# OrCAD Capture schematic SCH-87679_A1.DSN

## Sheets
1 4. BRKT-Sensors: size B; title: FRDM-STBI-A8971; rev: A1; company: NXP Semiconductors; note: SCH-87679 PDF: SPF-87679; note: 6501 William Cannon Drive West; note: Austin, TX 78735-8598
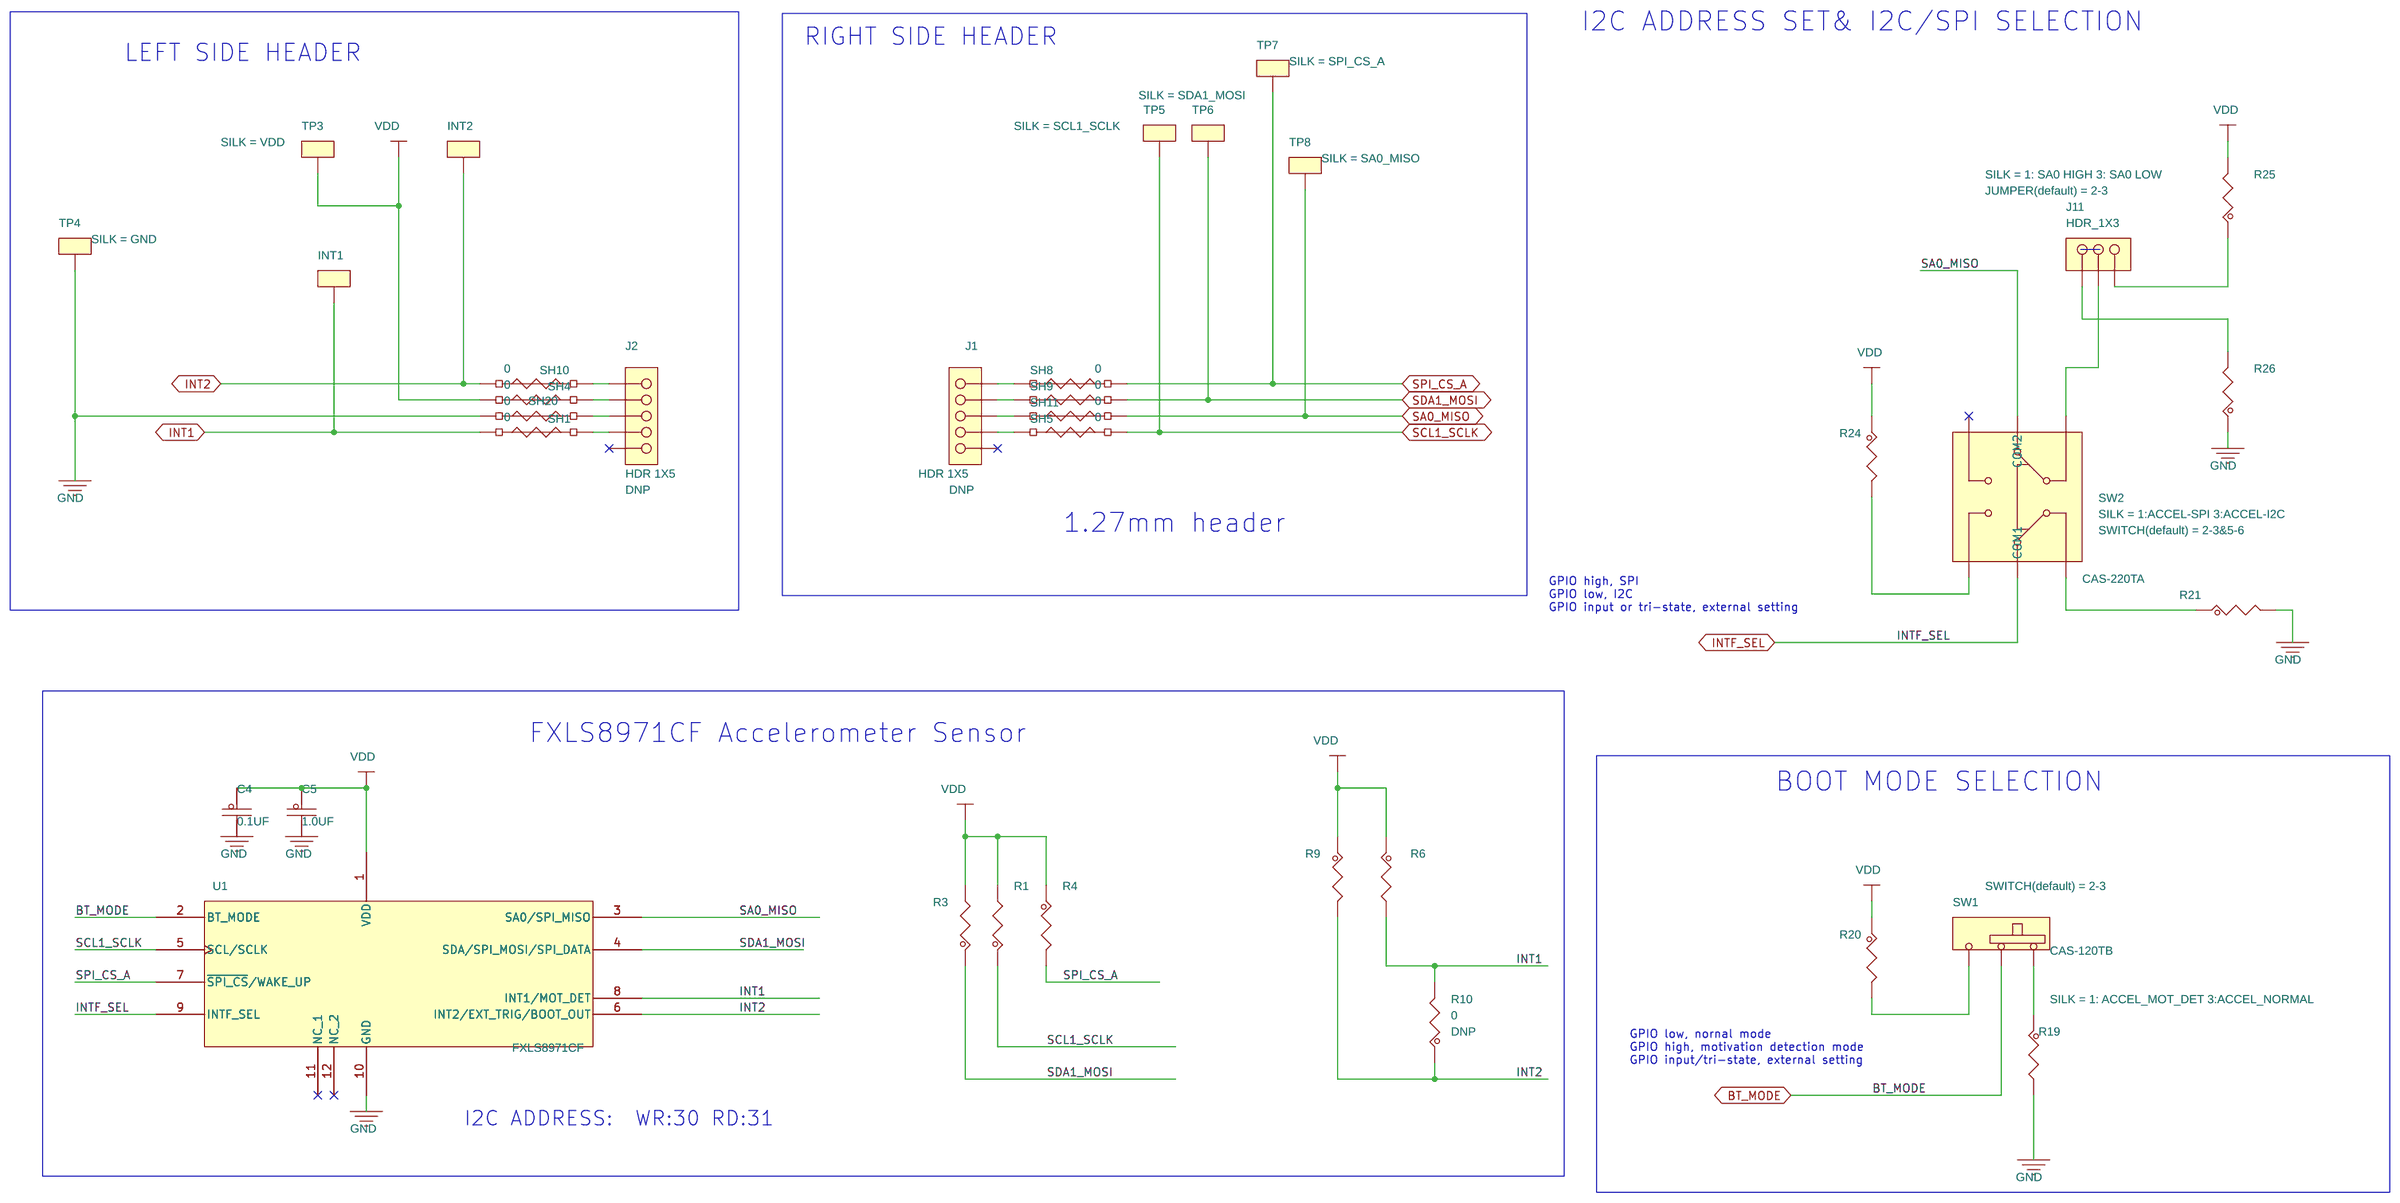
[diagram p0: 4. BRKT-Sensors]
2 1. Title Page
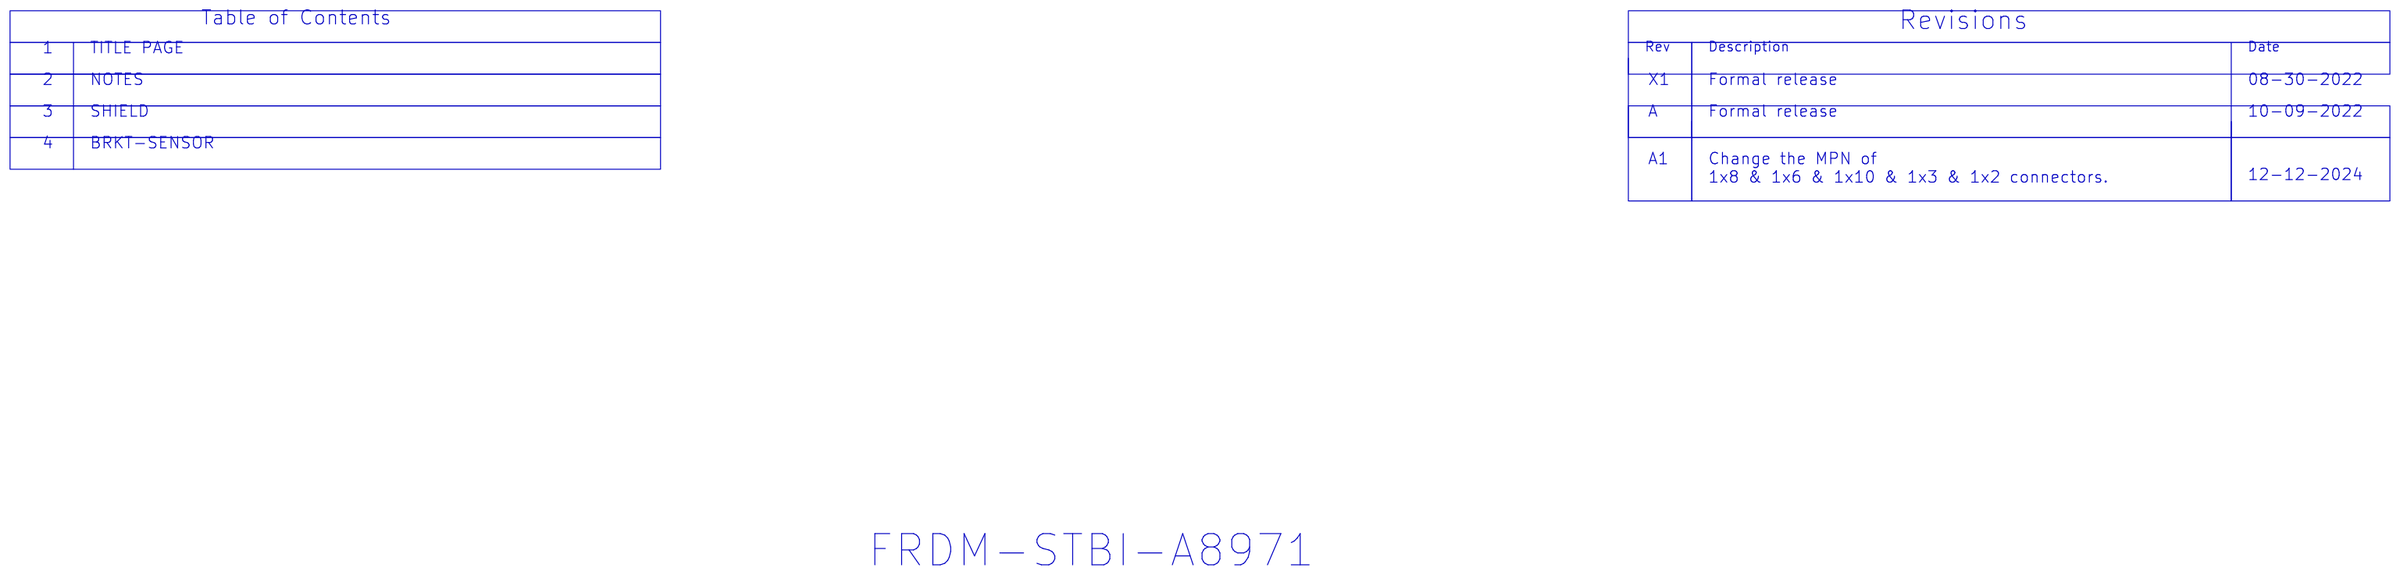
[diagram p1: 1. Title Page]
3 2. Notes
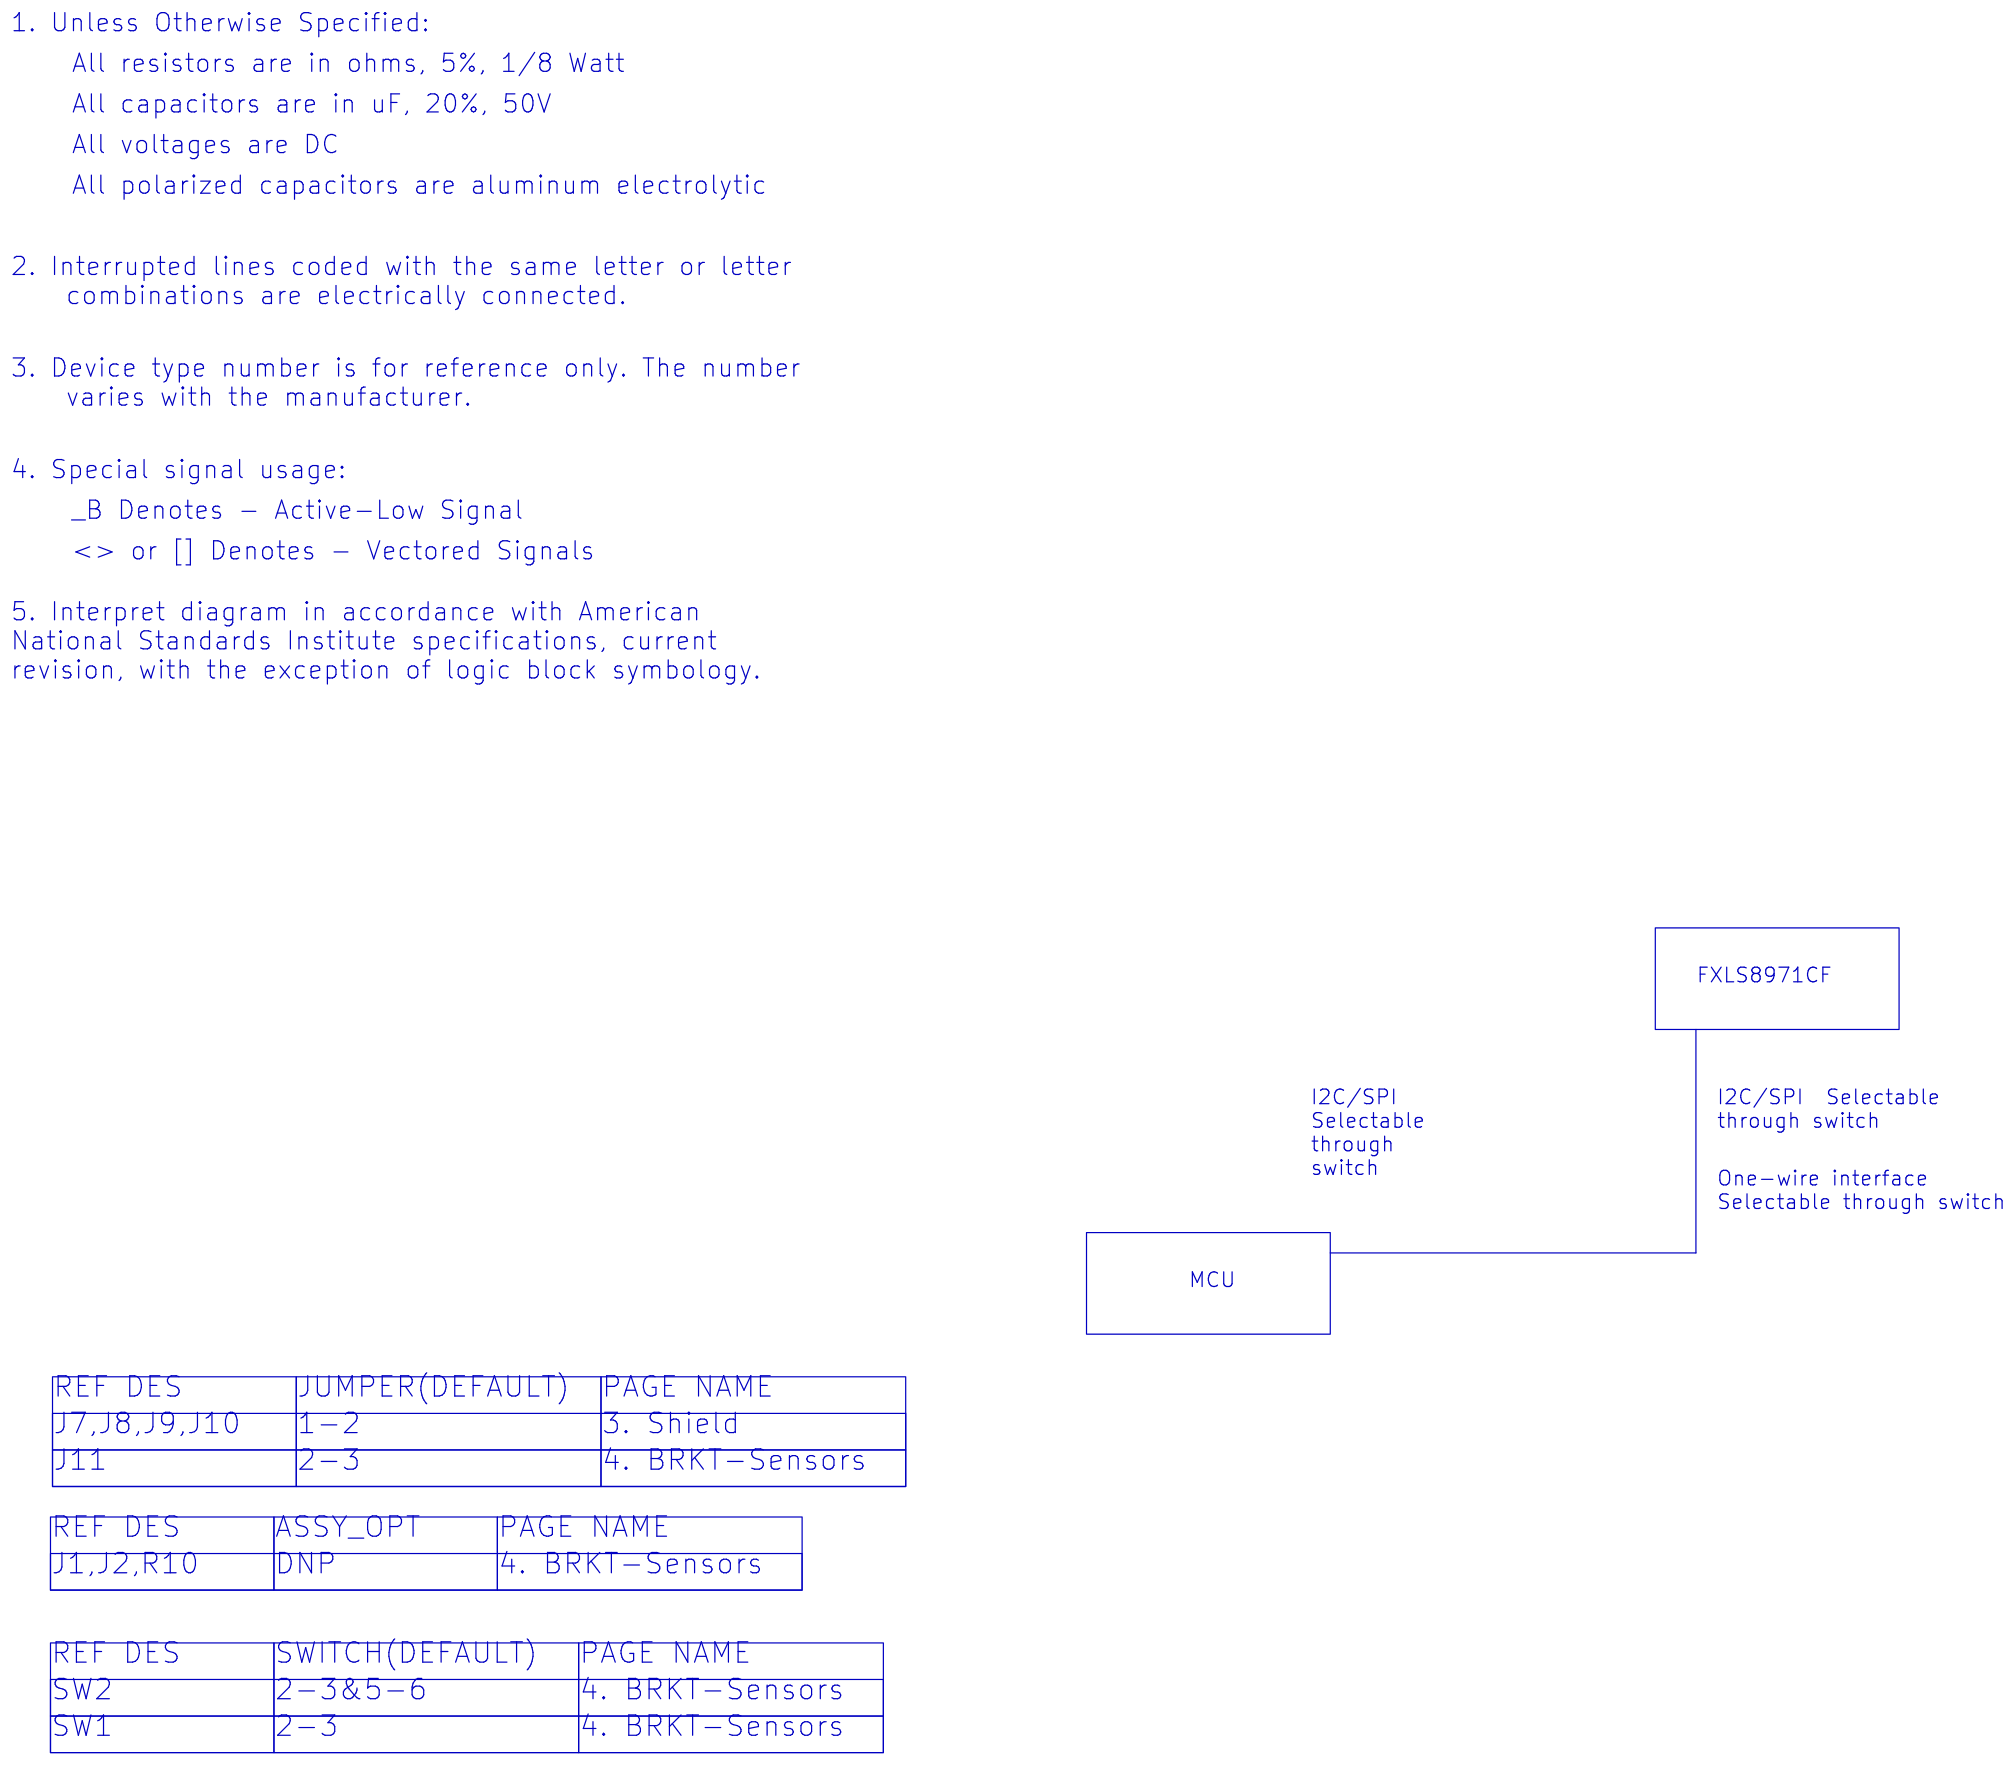
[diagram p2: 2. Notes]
4 3. Shield: size B
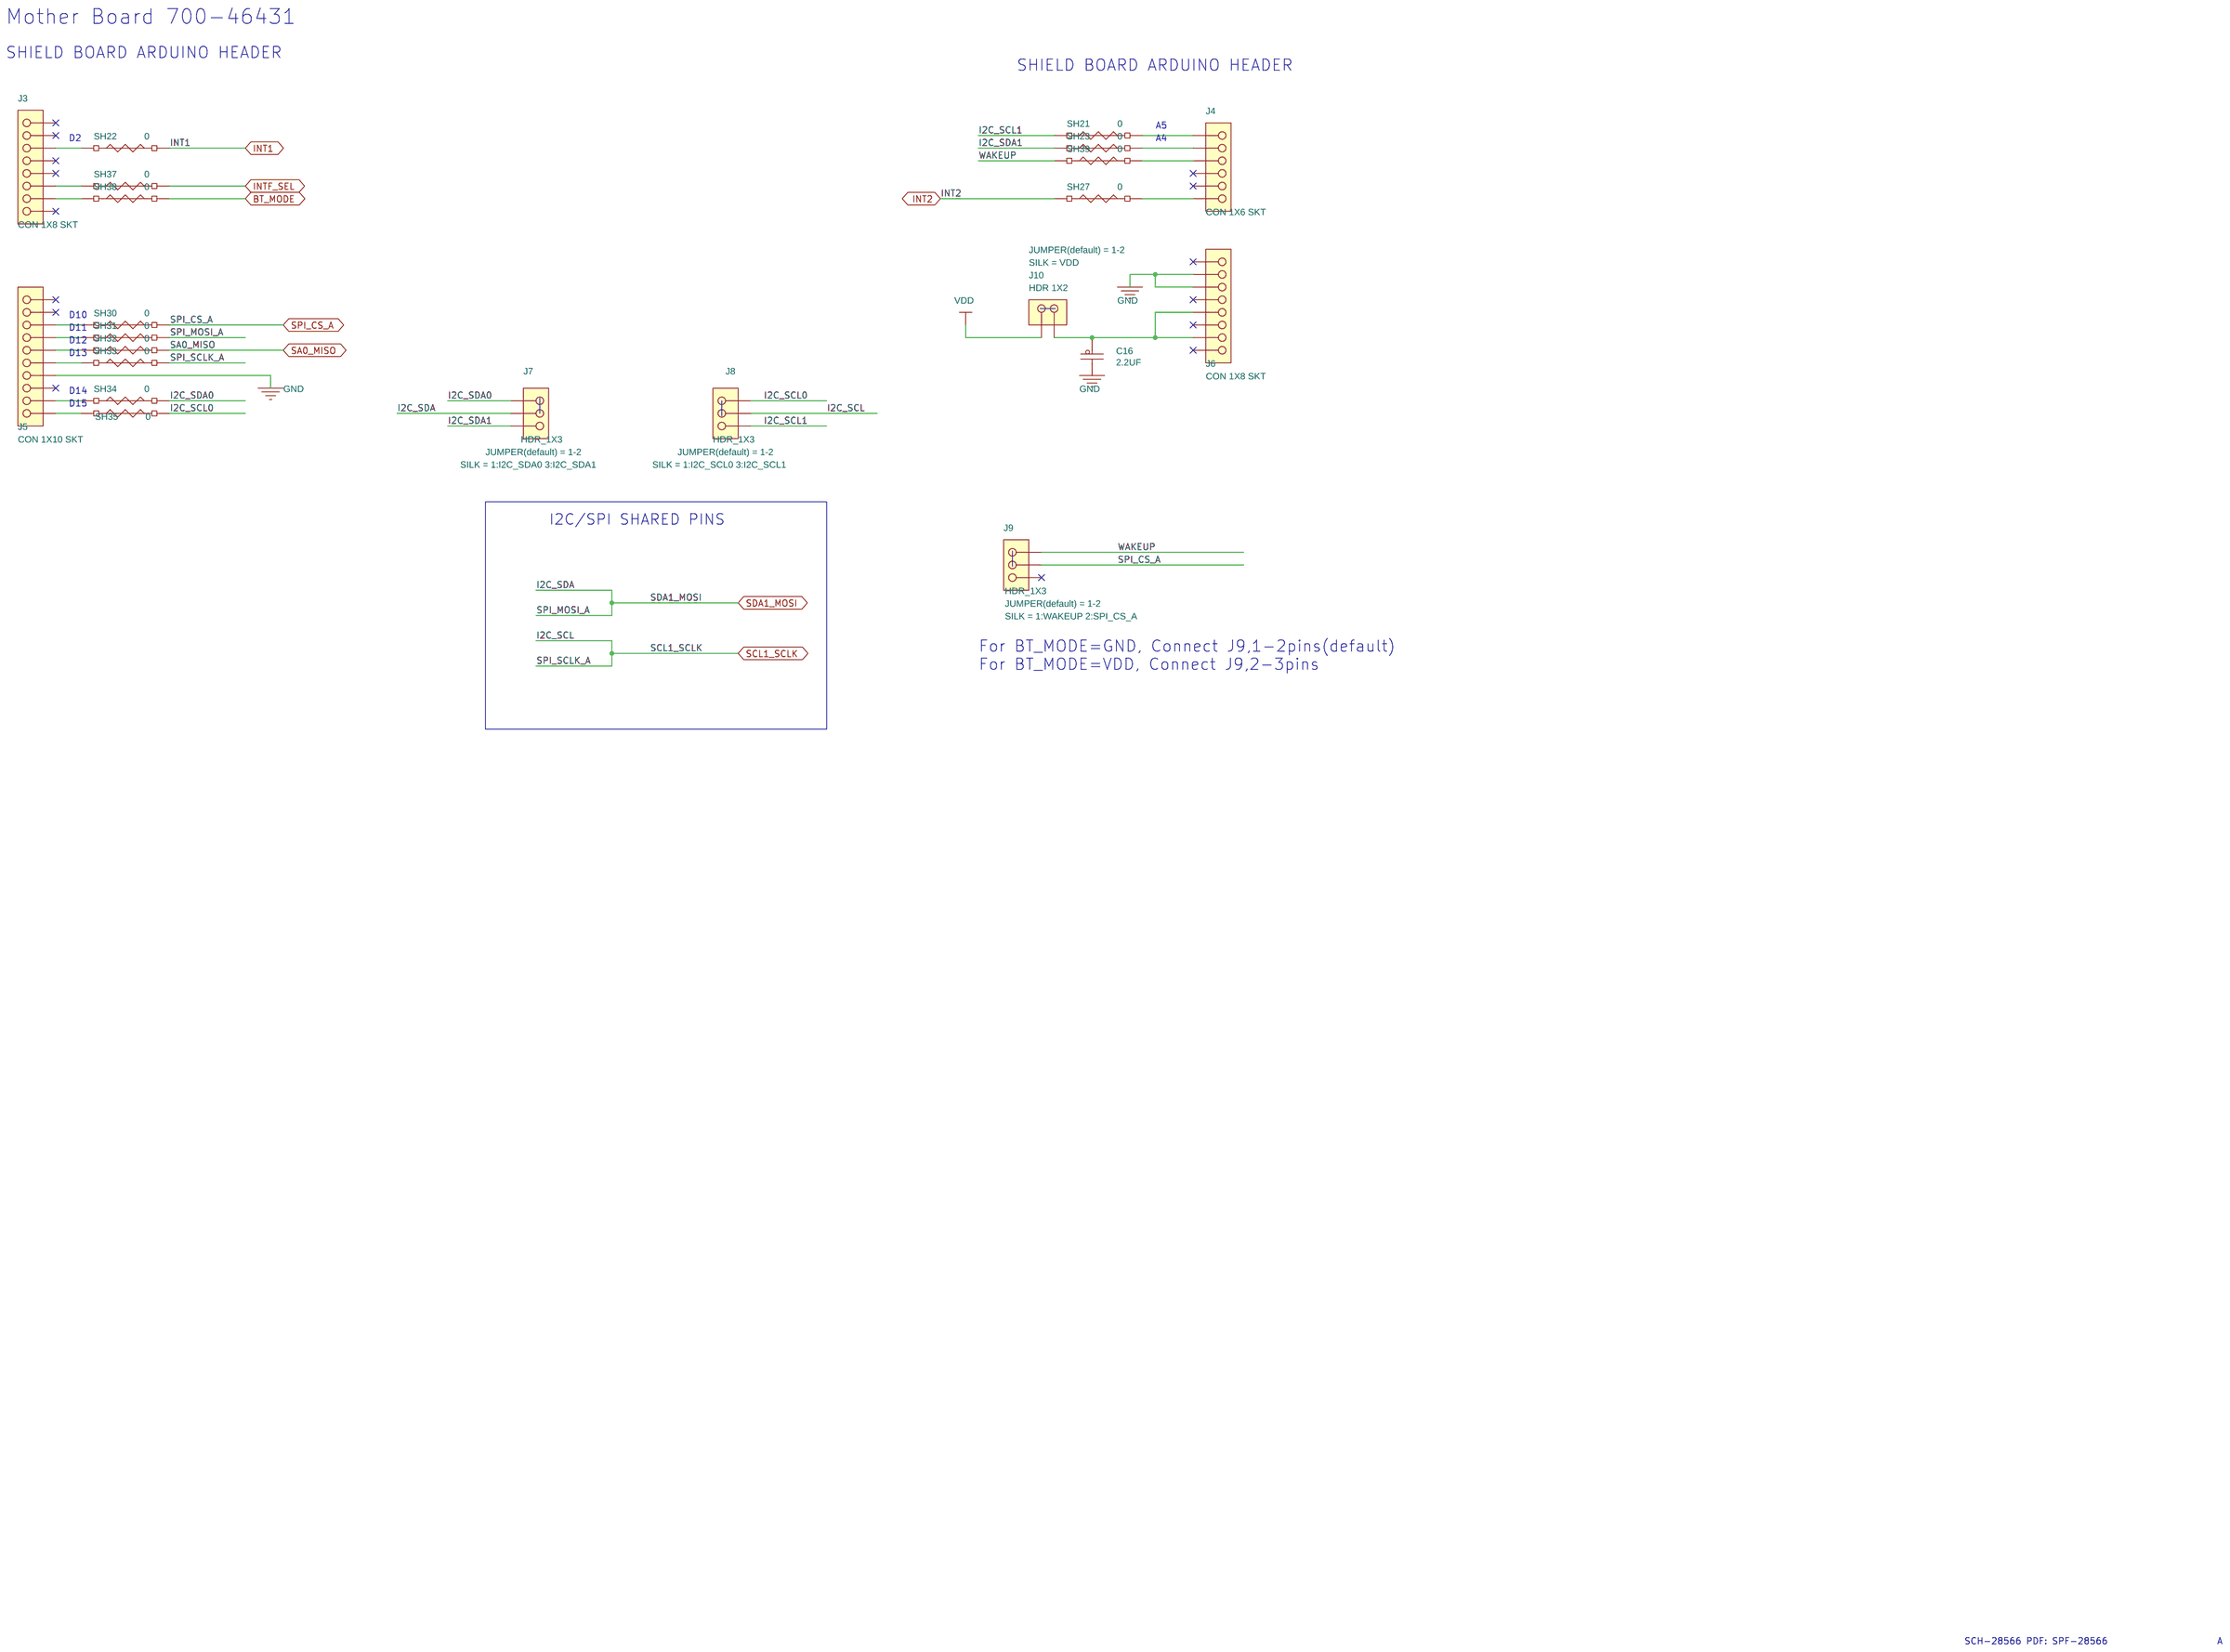
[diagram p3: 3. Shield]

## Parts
sheet 3. Shield
C16  2.2UF  [CC0402_25]
J3  CON 1X8 SKT  [con_skt1x8_th_394l]
J4  CON 1X6 SKT  [con_skt1x6_th_394l]
J5  CON 1X10 SKT  [hdr_1x10_2p54_341h]
J6  CON 1X8 SKT  [con_skt1x8_th_394l]
J7  HDR_1X3  [hdr103_330h]
J8  HDR_1X3  [hdr103_330h]
J9  HDR_1X3  [hdr103_330h]
J10  HDR 1X2  [hdr1x2_50mil]
SH21  0  [SH0201]
SH22  0  [SH0201]
SH23  0  [SH0201]
SH27  0  [SH0201]
SH30  0  [SH0201]
SH31  0  [SH0201]
SH32  0  [SH0201]
SH33  0  [SH0201]
SH34  0  [SH0201]
SH35  0  [SH0201]
SH37  0  [SH0201]
SH38  0  [SH0201]
SH39  0  [SH0201]
sheet 4. BRKT-Sensors
C4  0.1UF  [CC0402_25]
C5  1.0UF  [CC0402_25]
INT1  0805  [testpoint_122x049mil]
INT2  0805  [testpoint_122x049mil]
J1  HDR 1X5  [hdr1x5_50_th]
J2  HDR 1X5  [hdr1x5_50_th]
J11  HDR_1X3  [hdr103_330h]
R1  4.7K  [RC0603]
R3  4.7K  [RC0603]
R4  10K  [RC0603]
R6  10K  [RC0603]
R9  10K  [RC0603]
R10  0  [RC0603]
R19  10K  [RC0603]
R20  10K  [RC0603]
R21  10K  [RC0603]
R24  10K  [RC0603]
R25  10K  [RC0603]
R26  10K  [RC0603]
SH1  0  [SH0201]
SH4  0  [SH0201]
SH5  0  [SH0201]
SH8  0  [SH0201]
SH9  0  [SH0201]
SH10  0  [SH0201]
SH11  0  [SH0201]
SH20  0  [SH0201]
SW1  CAS-120TB  [sw3_1p75_3x6]
SW2  CAS-220TA  [sw6_1p75_4x5]
TP3  0805  [testpoint_122x049mil]
TP4  0805  [testpoint_122x049mil]
TP5  0805  [testpoint_122x049mil]
TP6  0805  [testpoint_122x049mil]
TP7  0805  [testpoint_122x049mil]
TP8  0805  [testpoint_122x049mil]
U1  FXLS8971CF  [qfn12_0p65_3x3]

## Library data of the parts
C16 = CAP_NP: CAP CER 2.2UF 6.3V 20% X5R 0402; AGILE_PN: 150-76792; CAD_APPROVED: Yes; FPLIST: CC0402_25,CC0402_HD,0402_CC; HEIGHT: 0.55; MFG_NAME01: KEMET; MFG_PN01: C0402C225M9PACTU; Package Size: 0402; ROHS: Yes; Rated Voltage: 6.3V; Temp Range: -55C to +85C; Tolerance: 20%; VOLTAGE: 6.3V
J3 J6 = CONN_HDR_8X1: CON 1X8 SKT SHRD TH 100MIL SP 343H AU 392L; 3D_Mechanical_Footprint_File: http://fcl.am.freescale.net/ALLEGRO/step/con_skt1x8_th_394l.STEP; AGILE_PN: 210-10329; Contact Voltage: 250V; HEIGHT: 8.7mm; MFG_NAME01: TOWNES ENTERPRICE CO.,LTD; MFG_PN01: F209-1*08SGF-0A-NH; Package Size: 20.82 x 2.54 mm; Package Type: PCB, Through Hole; ROHS: NULL; Temp Range: -25°C to 105°C
J4 = CONN_HDR_6X1: CON 1X6 SKT SHRD TH 100MIL SP 343H AU 392L; 3D_Mechanical_Footprint_File: http://fcl.am.freescale.net/ALLEGRO/step/con_skt1x6_th_394l.STEP; AGILE_PN: 210-10331; Contact Voltage: 250V; HEIGHT: 8.7mm; MFG_NAME01: TOWNES ENTERPRICE CO.,LTD; MFG_PN01: F209-1*06SGF-0A-NH; Package Size: 15.74 x 2.54 mm; Package Type: PCB, Through Hole; ROHS: NULL; Temp Range: -25°C to 105°C
J5 = CONN_HDR_10X1: CON 1X10 SKT SHRD TH 100MIL SP 341H AU 392L; 3D_Mechanical_Footprint_File: http://fcl.am.freescale.net/ALLEGRO/step/hdr_1x10_2p54_341h.STEP; AGILE_PN: 210-10330; CAD_APPROVED: Yes; Contact Voltage: 250 V AC/DC; HEIGHT: 8.65mm; MFG_NAME01: TOWNES ENTERPRICE CO.,LTD; MFG_PN01: F209-1*10SGF-0A-NH; Package Size: 25.9 x 2.54 mm; Package Type: Through Hole; ROHS: NULL; Temp Range: -25°C to 105°C
J7 = CONN_HDR_3X1: HDR 1X3 TH 100MIL SP 338H AU 98L; 3D_Mechanical_Footprint_File: http://fcl.am.freescale.net/ALLEGRO/step/hdr103_330h.STEP; AGILE_PN: 210-81491; CAD_APPROVED: Yes; FPLIST: hdr103_330h,HDR103,sh_hdr103_bottom_12,sh_hdr103_bottom_23; HEIGHT: 8.59; JUMPER(default): 1-2; MFG_NAME01: ANYTRONIC CORPORATION LIMITED; MFG_PN01: 0901S0203011N9T-31RF; ROHS: Yes; SILK: 1:I2C_SDA0 3:I2C_SDA1; Temp Range: -55°C to +105°C
J8 = CONN_HDR_3X1: HDR 1X3 TH 100MIL SP 338H AU 98L; 3D_Mechanical_Footprint_File: http://fcl.am.freescale.net/ALLEGRO/step/hdr103_330h.STEP; AGILE_PN: 210-81491; CAD_APPROVED: Yes; FPLIST: hdr103_330h,HDR103,sh_hdr103_bottom_12,sh_hdr103_bottom_23; HEIGHT: 8.59; JUMPER(default): 1-2; MFG_NAME01: ANYTRONIC CORPORATION LIMITED; MFG_PN01: 0901S0203011N9T-31RF; ROHS: Yes; SILK: 1:I2C_SCL0 3:I2C_SCL1; Temp Range: -55°C to +105°C
J9 = CONN_HDR_3X1: HDR 1X3 TH 100MIL SP 338H AU 98L; 3D_Mechanical_Footprint_File: http://fcl.am.freescale.net/ALLEGRO/step/hdr103_330h.STEP; AGILE_PN: 210-81491; CAD_APPROVED: Yes; FPLIST: hdr103_330h,HDR103,sh_hdr103_bottom_12,sh_hdr103_bottom_23; HEIGHT: 8.59; JUMPER(default): 1-2; MFG_NAME01: ANYTRONIC CORPORATION LIMITED; MFG_PN01: 0901S0203011N9T-31RF; ROHS: Yes; SILK: 1:WAKEUP 2:SPI_CS_A; Temp Range: -55°C to +105°C
J10 = CONN_HDR_2X1: HDR 1X2 TH 50MIL SP 165H AU 91L; 3D_Mechanical_Footprint_File: http://fcl.am.freescale.net/ALLEGRO/step/hdr1x2_50mil.STEP; AGILE_PN: 210-10169; CAD_APPROVED: Yes; Contact Voltage: 100V AC/DC; HEIGHT: 4.2mm; JUMPER(default): 1-2; MFG_NAME01: Townes Enterprice Co.,Ltd; MFG_PN01: P1031-1*02SGF-063A-X; Package Size: 2.1 x 2.54 mm; Package Type: PCB, Through Hole; ROHS: NULL; SILK: VDD; Temp Range: -40°C to 105°C
SH1 SH4 SH5 SH8-SH11 SH20-SH23 SH27 SH30-SH35 SH37-SH39 = RES_SHORT-2: ZERO OHM CUT TRACE 0201 PADS; NO PART TO ORDER; AGILE_PN: 470-76473; CAD_APPROVED: Yes; FPLIST: SH0201,SH0201_CC; HEIGHT: 0.1; ROHS: Yes
C4 = CAP_NP: CAP CER 0.1UF 10V 10% X5R 0402; AGILE_PN: 150-75634; CAD_APPROVED: Yes; FPLIST: CC0402_25,CC0402_HD,0402_CC; HEIGHT: 0.64; MFG_NAME01: KEMET; MFG_PN01: C0402C104K8PAC; Package Size: 0402; ROHS: Yes; Rated Voltage: 10V; Temp Range: -55C to +85C; Tolerance: 10%; VOLTAGE: 10V
C5 = CAP_NP: CAP CER 1.0UF 10V 10% X5R 0402; AGILE_PN: 150-75772; CAD_APPROVED: Yes; FPLIST: CC0402_25,CC0402_HD,0402_CC; HEIGHT: 0.6; MFG_NAME01: YAGEO AMERICA; MFG_PN01: CC0402KRX5R6BB105; Package Size: 0402; ROHS: Yes; Rated Voltage: 10V; Temp Range: -55C to +85C; Tolerance: 10%; VOLTAGE: 10V
INT1 INT2 = TEST_POINT: TEST POINT PAD 3.1MMX1.25MM SMT AEC-Q200 0805; 3D_Mechanical_Footprint_File: http://fcl.am.freescale.net/ALLEGRO/step/testpoint_122x049mil.STEP; AGILE_PN: 211-79608; CAD_APPROVED: Yes; HEIGHT: 1.45; MFG_NAME01: KOA SPEER; MFG_PN01: RCTCTE; Package Size: 2X1.25x1.45MM; Package Type: SMT; ROHS: Yes
J1 J2 = CONN_HDR_5X1: HDR 1X5 TH 50MIL SP 159H AU 90L; 3D_Mechanical_Footprint_File: http://fcl.am.freescale.net/ALLEGRO/step/hdr1x5_50_th.STEP; AGILE_PN: 210-82660; ASSY_OPT: DNP; CAD_APPROVED: Yes; HEIGHT: 4.04; MFG_NAME01: SAMTEC; MFG_PN01: FTS-105-01-L-S; Package Type: Through Hole; ROHS: Yes; Temp Range: -55°C to +125°C
J11 = CONN_HDR_3X1: HDR 1X3 TH 100MIL SP 338H AU 98L; 3D_Mechanical_Footprint_File: http://fcl.am.freescale.net/ALLEGRO/step/hdr103_330h.STEP; AGILE_PN: 210-81491; CAD_APPROVED: Yes; FPLIST: hdr103_330h,HDR103,sh_hdr103_bottom_12,sh_hdr103_bottom_23; HEIGHT: 8.59; JUMPER(default): 2-3; MFG_NAME01: ANYTRONIC CORPORATION LIMITED; MFG_PN01: 0901S0203011N9T-31RF; ROHS: Yes; SILK: 1: SA0 HIGH 3: SA0 LOW; Temp Range: -55°C to +105°C
R1 R3 = RES: RES MF 4.7K 1/10W 5% 0603; AGILE_PN: 470-75414; CAD_APPROVED: Yes; FPLIST: RC0603_OV,RC0603,0603_CC; HEIGHT: 0.55; MFG_NAME01: BOURNS; MFG_PN01: CR0603-JW-472ELF; ROHS: Yes; Tolerance: 5%
R4 R6 R9 R19-R21 R24-R26 = RES: RES MF 10K 1/10W 5% 0603; AGILE_PN: 470-75410; CAD_APPROVED: Yes; FPLIST: RC0603_OV,RC0603,0603_CC; HEIGHT: 0.55; MFG_NAME01: BOURNS; MFG_PN01: CR0603-JW-103ELF; ROHS: Yes; Temp Range: –55 °C to +155 °C; Tolerance: 5%
R10 = RES: RES MF ZERO OHM 1/10W 1% 0603; AGILE_PN: 470-80217; ASSY_OPT: DNP; CAD_APPROVED: Yes; FPLIST: RC0603_OV,RC0603,R603-X2,0603_CC; HEIGHT: 0.55; MFG_NAME01: MULTICOMP; MFG_PN01: MC0603SAF0000T5E; ROHS: Yes; Tolerance: 1%
SW1 = SW3_SPDT_SLD: SW SPDT SLD 100MA 6V SMD; 3D_Mechanical_Footprint_File: http://fcl.am.freescale.net/ALLEGRO/step/sw3_1p75_3x6.STEP; AGILE_PN: 510-78101; ASSY_NOTE: 2-3; CAD_APPROVED: Yes; HEIGHT: 2.5; MFG_NAME01: NIDEC COPAL ELECTRONICS CORP; ROHS: Yes; SILK: 1: ACCEL_MOT_DET 3:ACCEL_NORMAL; SWITCH(default): 2-3
SW2 = SW_SL_DPDT_6P: SW DPDT SLIDE 24VDC 25mA SMD; 3D_Mechanical_Footprint_File: http://fcl.am.freescale.net/ALLEGRO/step/sw6_1p75_4x5.step; AGILE_PN: 510-78098; CAD_APPROVED: Yes; HEIGHT: 2.5; MFG_NAME01: NIDEC COPAL ELECTRONICS CORP; ROHS: Yes; SILK: 1:ACCEL-SPI 3:ACCEL-I2C; SWITCH(default): 2-3&5-6; Temp Range: -40 to +85&#8451;; Temp_Range: -40 to +85&#8451;
TP3 = TEST_POINT: TEST POINT PAD 3.1MMX1.25MM SMT AEC-Q200 0805; 3D_Mechanical_Footprint_File: http://fcl.am.freescale.net/ALLEGRO/step/testpoint_122x049mil.STEP; AGILE_PN: 211-79608; CAD_APPROVED: Yes; HEIGHT: 1.45; MFG_NAME01: KOA SPEER; MFG_PN01: RCTCTE; Package Size: 2X1.25x1.45MM; Package Type: SMT; ROHS: Yes; SILK: VDD
TP4 = TEST_POINT: TEST POINT PAD 3.1MMX1.25MM SMT AEC-Q200 0805; 3D_Mechanical_Footprint_File: http://fcl.am.freescale.net/ALLEGRO/step/testpoint_122x049mil.STEP; AGILE_PN: 211-79608; CAD_APPROVED: Yes; HEIGHT: 1.45; MFG_NAME01: KOA SPEER; MFG_PN01: RCTCTE; Package Size: 2X1.25x1.45MM; Package Type: SMT; ROHS: Yes; SILK: GND
TP5 = TEST_POINT: TEST POINT PAD 3.1MMX1.25MM SMT AEC-Q200 0805; 3D_Mechanical_Footprint_File: http://fcl.am.freescale.net/ALLEGRO/step/testpoint_122x049mil.STEP; AGILE_PN: 211-79608; CAD_APPROVED: Yes; HEIGHT: 1.45; MFG_NAME01: KOA SPEER; MFG_PN01: RCTCTE; Package Size: 2X1.25x1.45MM; Package Type: SMT; ROHS: Yes; SILK: SCL1_SCLK
TP6 = TEST_POINT: TEST POINT PAD 3.1MMX1.25MM SMT AEC-Q200 0805; 3D_Mechanical_Footprint_File: http://fcl.am.freescale.net/ALLEGRO/step/testpoint_122x049mil.STEP; AGILE_PN: 211-79608; CAD_APPROVED: Yes; HEIGHT: 1.45; MFG_NAME01: KOA SPEER; MFG_PN01: RCTCTE; Package Size: 2X1.25x1.45MM; Package Type: SMT; ROHS: Yes; SILK: SDA1_MOSI
TP7 = TEST_POINT: TEST POINT PAD 3.1MMX1.25MM SMT AEC-Q200 0805; 3D_Mechanical_Footprint_File: http://fcl.am.freescale.net/ALLEGRO/step/testpoint_122x049mil.STEP; AGILE_PN: 211-79608; CAD_APPROVED: Yes; HEIGHT: 1.45; MFG_NAME01: KOA SPEER; MFG_PN01: RCTCTE; Package Size: 2X1.25x1.45MM; Package Type: SMT; ROHS: Yes; SILK: SPI_CS_A
TP8 = TEST_POINT: TEST POINT PAD 3.1MMX1.25MM SMT AEC-Q200 0805; 3D_Mechanical_Footprint_File: http://fcl.am.freescale.net/ALLEGRO/step/testpoint_122x049mil.STEP; AGILE_PN: 211-79608; CAD_APPROVED: Yes; HEIGHT: 1.45; MFG_NAME01: KOA SPEER; MFG_PN01: RCTCTE; Package Size: 2X1.25x1.45MM; Package Type: SMT; ROHS: Yes; SILK: SA0_MISO
U1 = FXLS8971CF_QFN12: IC ACCELEROMETER 3-AXIS LOW-G QFN12; 3D_Mechanical_Footprint_File: http://fcl.am.freescale.net/ALLEGRO/step/qfn12_0p65_3x3.step; AGILE_PN: TMP-CIP-12217; CAD_APPROVED: Yes; HEIGHT: 1.3; MFG_NAME01: NXP SEMICONDUCTORS; PRE_APN: 312-83713; Package Size: 3mmx3mmx1mm; ROHS: Yes

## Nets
GND: C4.2 C5.2 C16.2 J5.7 J6.6 J6.7 R19.2 R21.2 R26.1 SH20.2 TP4.1 U1.10(GND)
VDD: C4.1 C5.1 J10.1 R1.2 R3.2 R4.1 R6.1 R9.1 R20.1 R24.1 R25.2 SH4.2 TP3.1 U1.1(VDD)
BT_MODE: SH38.2 SW1.2 U1.2(BT_MODE)
I2C_SCL0: J8.1 SH35.2
I2C_SCL1: J8.3 SH21.1
I2C_SDA0: J7.1 SH34.2
I2C_SDA1: J7.3 SH23.1
INT1: INT1.1 R6.2 R10.2 SH1.2 SH22.2 U1.8(INT1/MOT_DET)
INT2: INT2.1 R9.2 R10.1 SH10.2 SH27.1 U1.6(INT2/EXT_TRIG/BOOT_OUT)
INTF_SEL: SH37.2 SW2.2(COM1) U1.9(INTF_SEL)
SA0_MISO: SH11.2 SH32.2 SW2.5(COM2) TP8.1 U1.3(SA0/SPI_MISO)
SCL1_SCLK: J8.2 R1.1 SH5.2 SH33.2 TP5.1 U1.5(SCL/SCLK)
SDA1_MOSI: J7.2 R3.1 SH9.2 SH31.2 TP6.1 U1.4(SDA/SPI_MOSI/SPI_DATA)
SPI_CS_A: J9.2 R4.2 SH8.2 SH30.2 TP7.1 U1.7(~{SPI_CS}/WAKE_UP)
WAKEUP: J9.1 SH39.1
N00622: J5.9 SH34.1
N00628: J5.10 SH35.1
N00993: C16.1 J6.2 J6.4 J10.2
N05692: J4.6 SH21.2
N05729: J4.5 SH23.2
N16652859: J5.4 SH31.1
N16652885: J5.5 SH32.1
N16652889: J5.6 SH33.1
N16653001: J5.3 SH30.1
N16659634: J4.1 SH27.2
N16701284: J3.3 SH22.1
N16711839: J2.1 SH10.1
N16711841: J2.2 SH4.1
N16711843: J2.3 SH20.1
N16711845: J2.4 SH1.1
N16711871: J1.1 SH8.1
N16711873: J1.2 SH9.1
N16711875: J1.3 SH11.1
N16711877: J1.4 SH5.1
N16715705: R20.2 SW1.1
N16718521: R21.1 SW2.3
N16718681: R24.2 SW2.1
N16719014: J11.2 SW2.6
N16720544: J3.6 SH37.1
N16720548: J3.7 SH38.1
N16721741: J4.4 SH39.2
N16750690: J11.1 R25.1
N16750694: J11.3 R26.2
N16884640: R19.1 SW1.3

Not connected (* = marked no-connect by the designer): J1 5*; J2 5*; J3 1* 2* 4* 5* 8*; J4 2* 3*; J5 1* 2* 8*; J6 1* 3* 5* 8*; J9 3*; SW2 4*; U1 11(NC_1)* 12(NC_2)*

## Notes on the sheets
sheet 1
- I2C ADDRESS SET& I2C/SPI SELECTION
- RIGHT SIDE HEADER
- LEFT SIDE HEADER
- 1.27mm header
- GPIO high, SPI
  GPIO low, I2C
  GPIO input or tri-state, external setting
- FXLS8971CF Accelerometer Sensor
- BOOT MODE SELECTION
- GPIO low, nornal mode
  GPIO high, motivation detection mode
  GPIO input/tri-state, external setting
- I2C ADDRESS:  WR:30 RD:31
sheet 2
- Table of Contents
- Revisions
- 1
- TITLE PAGE
- Rev
- Description
- Date
- 2
- NOTES
- X1
- Formal release
- 08-30-2022
- 3
- SHIELD
- A
- Formal release
- 10-09-2022
- 4
- BRKT-SENSOR
- A1
- Change the MPN of
  1x8 & 1x6 & 1x10 & 1x3 & 1x2 connectors.
- 12-12-2024
- FRDM-STBI-A8971
sheet 3
- 1. Unless Otherwise Specified:
- All resistors are in ohms, 5%, 1/8 Watt
- All capacitors are in uF, 20%, 50V
- All voltages are DC
- All polarized capacitors are aluminum electrolytic
- 2. Interrupted lines coded with the same letter or letter
      combinations are electrically connected.
- 3. Device type number is for reference only. The number
      varies with the manufacturer.
- 4. Special signal usage:
- _B Denotes - Active-Low Signal
- <> or [] Denotes - Vectored Signals
- 5. Interpret diagram in accordance with American
  National Standards Institute specifications, current
  revision, with the exception of logic block symbology.
- FXLS8971CF
- I2C/SPI
  Selectable
  through
  switch
- I2C/SPI  Selectable
  through switch
- One-wire interface
  Selectable through switch
- MCU
- REF DES
- JUMPER(DEFAULT)
- PAGE NAME
- J7,J8,J9,J10
- 1-2
- 3. Shield
- J11
- 2-3
- 4. BRKT-Sensors
- REF DES
- ASSY_OPT
- PAGE NAME
- J1,J2,R10
- DNP
- 4. BRKT-Sensors
- REF DES
- SWITCH(DEFAULT)
- PAGE NAME
- SW2
- 2-3&5-6
- 4. BRKT-Sensors
- SW1
- 2-3
- 4. BRKT-Sensors
sheet 4
- Mother Board 700-46431
- SHIELD BOARD ARDUINO HEADER
- SHIELD BOARD ARDUINO HEADER
- A5
- D2
- A4
- D10
- D11
- D12
- D13
- D14
- D15
- I2C/SPI SHARED PINS
- For BT_MODE=GND, Connect J9,1-2pins(default)
  For BT_MODE=VDD, Connect J9,2-3pins
- SCH-28566 PDF: SPF-28566
- A
